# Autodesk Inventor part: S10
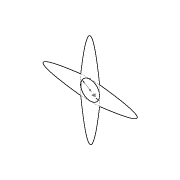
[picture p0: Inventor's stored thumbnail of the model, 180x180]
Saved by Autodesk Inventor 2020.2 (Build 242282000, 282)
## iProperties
Created: 2013-12
Part Number: S10
Material: Ogólny
Document SubType Name: Modeling
Designer: F.Stasiak
Density: 1 g/cm^3
Appearance: Domyślna
Manager: www.cadconsulting.pl
Company: Fabian Stasiak CAD Consulting
Author: F.Stasiak
Subject: Zbiór ćwiczeń. Autodesk Inventor 2020. Kurs podstawowy
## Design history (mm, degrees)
sketch "Szkic1" dims "d7" = -200, "d8" = 200, "d9" = -200, "d10" = 200, "d11" = -200, "d12" = 200
  geometry: L1 (-20, 20)-(20, 20); L2 (20, 20)-(20, -20); L3 (20, -20)-(-20, -20); L4 (-20, -20)-(-20, 20); C1 r 20 at (0, 0); 3 further points
  constraints: 8 end point, 3 horizontal alignment, 3 vertical alignment, 2 midpoint, 2 parallel, 1 centre point, 1 coincident, 1 horizontal, 1 perpendicular, 8 other
  dimensions: "d0" = 40 diameter of C1
  node "Krzywa z równania 2D1" dims "d1" = -200, "d2" = 200
